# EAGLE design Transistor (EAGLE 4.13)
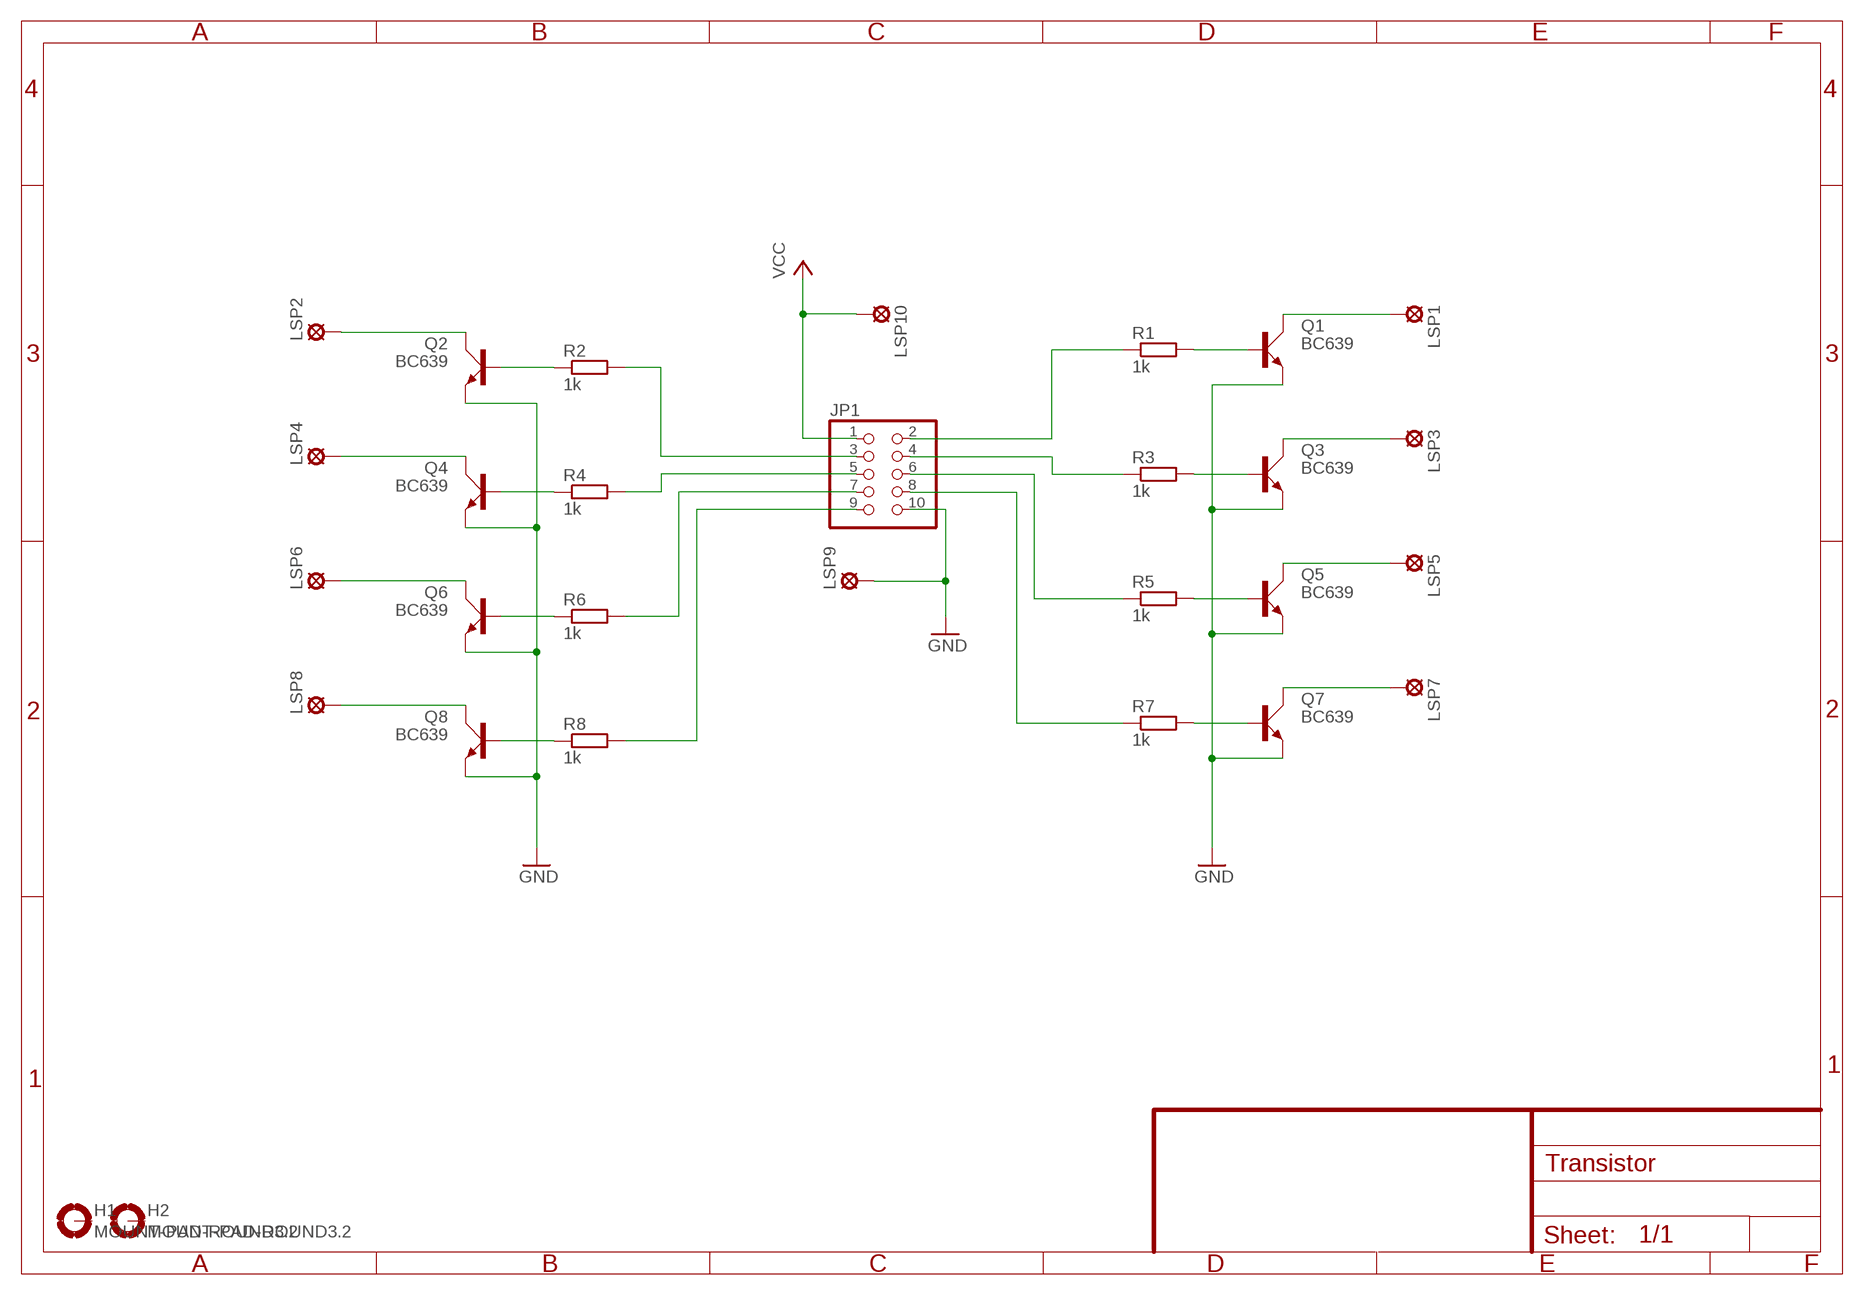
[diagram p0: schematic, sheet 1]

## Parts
H1  MOUNT-PAD-ROUND3.2  [3,2-PAD]
H2  MOUNT-PAD-ROUND3.2  [3,2-PAD]
JP1  PINHD-2X5  [2X05]
LSP1  LSP13  [LSP13]
LSP2  LSP13  [LSP13]
LSP3  LSP13  [LSP13]
LSP4  LSP13  [LSP13]
LSP5  LSP13  [LSP13]
LSP6  LSP13  [LSP13]
LSP7  LSP13  [LSP13]
LSP8  LSP13  [LSP13]
LSP9  LSP13  [LSP13]
LSP10  LSP13  [LSP13]
Q1  BC639  [SOT54D]
Q2  BC639  [SOT54D]
Q3  BC639  [SOT54D]
Q4  BC639  [SOT54D]
Q5  BC639  [SOT54D]
Q6  BC639  [SOT54D]
Q7  BC639  [SOT54D]
Q8  BC639  [SOT54D]
R1  1k  R-EU_0204/2V  [0204V]
R2  1k  R-EU_0204/2V  [0204V]
R3  1k  R-EU_0204/2V  [0204V]
R4  1k  R-EU_0204/2V  [0204V]
R5  1k  R-EU_0204/2V  [0204V]
R6  1k  R-EU_0204/2V  [0204V]
R7  1k  R-EU_0204/2V  [0204V]
R8  1k  R-EU_0204/2V  [0204V]

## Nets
GND: JP1.10 LSP9.MP Q1.E Q2.E Q3.E Q4.E Q5.E Q6.E Q7.E Q8.E
N$1: JP1.2 R1.1
N$2: JP1.4 R3.1
N$3: JP1.6 R5.1
N$4: JP1.8 R7.1
N$5: JP1.3 R2.2
N$6: JP1.5 R4.2
N$7: JP1.7 R6.2
N$8: Q2.B R2.1
N$9: Q4.B R4.1
N$10: Q6.B R6.1
N$11: Q8.B R8.1
N$12: Q1.B R1.2
N$13: Q3.B R3.2
N$14: JP1.9 R8.2
N$15: Q5.B R5.2
N$16: Q7.B R7.2
N$19: LSP2.MP Q2.C
N$20: LSP4.MP Q4.C
N$21: LSP6.MP Q6.C
N$22: LSP8.MP Q8.C
N$23: LSP7.MP Q7.C
N$24: LSP5.MP Q5.C
N$25: LSP3.MP Q3.C
N$26: LSP1.MP Q1.C
VCC: JP1.1 LSP10.MP
Unconnected: H1.B3,2(MOUNT) H2.B3,2(MOUNT)

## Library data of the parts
H1 H2 = holes:MOUNT-PAD-ROUND: MOUNTING PAD, round
JP1 = pinhead:PINHD-2X5: PIN HEADER
LSP1-LSP10 = solpad:LSP13: SOLDER PAD
Q1-Q8 = transistor-small-signal:BC639: NPN TRANSISTOR
R1-R8 = rcl:R-EU_: RESISTOR, European symbol

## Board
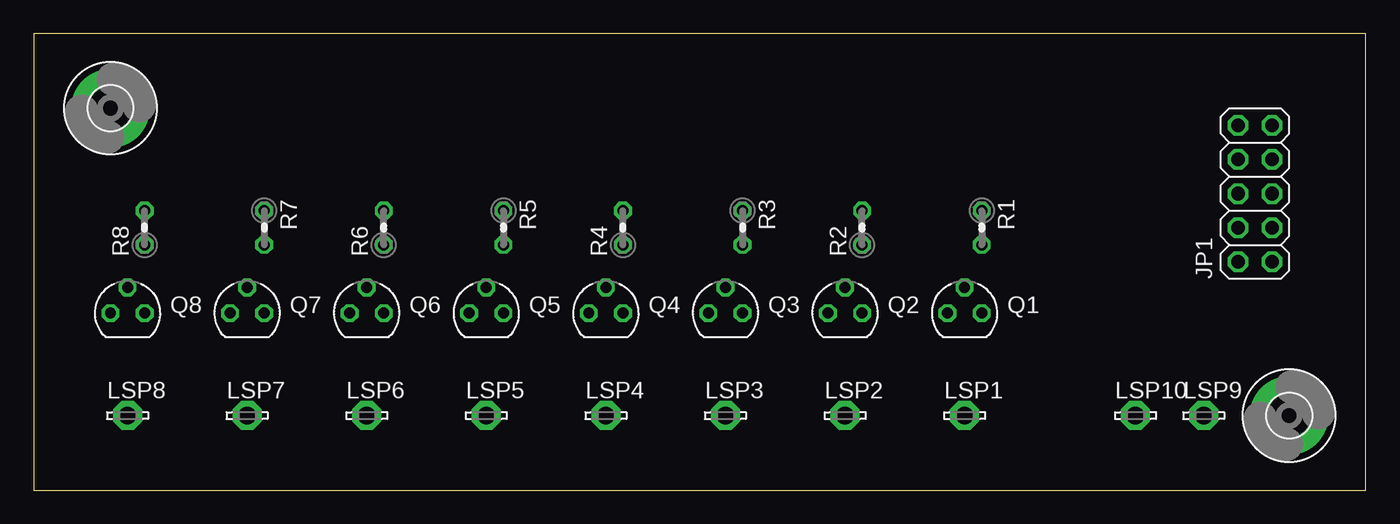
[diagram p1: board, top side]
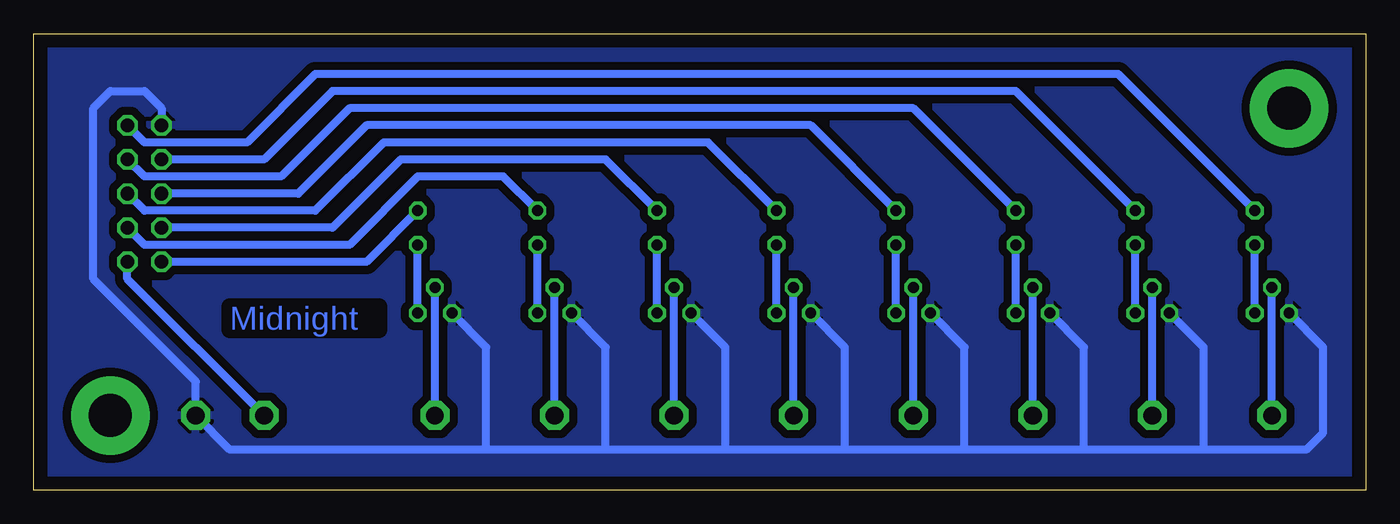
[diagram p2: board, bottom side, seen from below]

Size 99.04 x 33.96 mm. Coordinates in mm from the lower left corner, seen from the top.
Outline: 0,0 99.04,0 99.04,33.96 0,33.96 0,0
Copper layers (1*16): Top 0.035mm / dielectric 1.5mm / Bottom 0.035mm
Design rules "default": minimum track width 10mil, minimum drill 24mil, track to track 8mil, track to pad 8mil, pad to pad 8mil, via to via 8mil, smd to smd 8mil, copper to edge 40mil, drill to drill 8mil, minimum pad ring 10mil, minimum via ring 8mil, stop-mask expansion 4mil, vias tented up to drill 0mil, thermal gap 10mil

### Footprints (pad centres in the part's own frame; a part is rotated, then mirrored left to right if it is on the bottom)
3,2-PAD = drill 3.2 pad 5.842 round: B3,2 0,0
2X05 = drill 1.016 octagon: 1 -5.08,-1.27; 2 -5.08,1.27; 3 -2.54,-1.27; 4 -2.54,1.27; 5 0,-1.27; 6 0,1.27; 7 2.54,-1.27; 8 2.54,1.27; 9 5.08,-1.27; 10 5.08,1.27
LSP13 = drill 1.321 pad 2.159 octagon: MP 0,0
SOT54D = drill 0.813 octagon: B 1.27,0; C 0,1.905; E -1.27,0
0204V = drill 0.813 octagon: 1 -1.27,0; 2 1.27,0

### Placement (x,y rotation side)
H1  5.71,28.41 0 top
H2  93.34,5.55 0 top
JP1  90.8,22.06 90 top
LSP1  69.21,5.55 0 top
LSP2  60.32,5.55 0 top
LSP3  51.43,5.55 0 top
LSP4  42.54,5.55 0 top
LSP5  33.65,5.55 0 top
LSP6  24.76,5.55 0 top
LSP7  15.87,5.55 0 top
LSP8  6.98,5.55 0 top
LSP9  86.99,5.55 0 top
LSP10  81.91,5.55 0 top
Q1  69.21,13.17 0 top
Q2  60.32,13.17 0 top
Q3  51.43,13.17 0 top
Q4  42.54,13.17 0 top
Q5  33.65,13.17 0 top
Q6  24.76,13.17 0 top
Q7  15.87,13.17 0 top
Q8  6.98,13.17 0 top
R1  70.48,19.52 270 top
R2  61.59,19.52 90 top
R3  52.7,19.52 270 top
R4  43.81,19.52 90 top
R5  34.92,19.52 270 top
R6  26.03,19.52 90 top
R7  17.14,19.52 270 top
R8  8.25,19.52 90 top

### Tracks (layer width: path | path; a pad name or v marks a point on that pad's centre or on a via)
GND
  Bottom 0.61: Q6.E 20.95,10.63 20.95,3.01 | 20.95,3.01 29.84,3.01 | Q5.E 29.84,10.63 29.84,3.01 | 29.84,3.01 38.73,3.01 | Q4.E 38.73,10.63 38.73,3.01 | 38.73,3.01 47.62,3.01 | Q3.E 47.62,10.63 47.62,3.01 | 47.62,3.01 56.51,3.01 | Q2.E 56.51,10.63 56.51,3.01 | 56.51,3.01 65.4,3.01 | Q1.E 65.4,10.63 65.4,3.01 | 65.4,3.01 84.45,3.01 LSP9.MP 86.99,8.09 94.61,15.71 94.61,28.41 93.34,29.68 90.8,29.68 89.53,28.41 JP1.10 | Q8.E 3.17,10.63 3.17,4.28 4.44,3.01 12.06,3.01 | 12.06,3.01 20.95,3.01 | Q7.E 12.06,10.63 12.06,3.01
  pour Bottom (isolate 0.61): 0.63,33.49 98.42,33.49 98.42,0.47 0.63,0.47
N$1
  Bottom 0.61: R1.1 74.29,16.98 JP1.2
N$2
  Bottom 0.61: R3.1 56.51,24.6 71.75,24.6 76.83,19.52 JP1.4
N$3
  Bottom 0.61: R5.1 41.27,27.14 74.29,27.14 79.37,22.06 JP1.6
N$4
  Bottom 0.61: R7.1 26.03,29.68 76.83,29.68 81.91,24.6 JP1.8
N$5
  Bottom 0.61: R2.2 64.13,23.33 70.48,23.33 75.56,18.25 90.8,18.25 JP1.3
N$6
  Bottom 0.61: R4.2 48.89,25.87 73.02,25.87 78.1,20.79 90.8,20.79 JP1.5
N$7
  Bottom 0.61: R6.2 33.65,28.41 75.56,28.41 80.64,23.33 90.8,23.33 JP1.7
N$8
  Bottom 0.61: Q2.B R2.1
N$9
  Bottom 0.61: Q4.B R4.1
N$10
  Bottom 0.61: Q6.B R6.1
N$11
  Bottom 0.61: Q8.B R8.1
N$12
  Bottom 0.61: Q1.B R1.2
N$13
  Bottom 0.61: Q3.B R3.2
N$14
  Bottom 0.61: R8.2 18.41,30.95 78.1,30.95 83.18,25.87 90.8,25.87 JP1.9
N$15
  Bottom 0.61: Q5.B R5.2
N$16
  Bottom 0.61: Q7.B R7.2
N$19
  Bottom 0.61: LSP2.MP Q2.C
N$20
  Bottom 0.61: LSP4.MP Q4.C
N$21
  Bottom 0.61: LSP6.MP Q6.C
N$22
  Bottom 0.61: LSP8.MP Q8.C
N$23
  Bottom 0.61: LSP7.MP Q7.C
N$24
  Bottom 0.61: LSP5.MP Q5.C
N$25
  Bottom 0.61: LSP3.MP Q3.C
N$26
  Bottom 0.61: LSP1.MP Q1.C
VCC
  Bottom 0.61: LSP10.MP 92.07,15.71 JP1.1

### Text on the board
Bottom: Midnight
